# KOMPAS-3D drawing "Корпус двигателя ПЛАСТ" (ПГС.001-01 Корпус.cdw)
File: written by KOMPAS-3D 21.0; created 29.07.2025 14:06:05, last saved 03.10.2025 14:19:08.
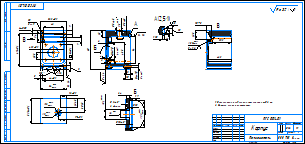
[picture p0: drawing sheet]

Sheet 1: A4x3, landscape

Document properties: Автор: rinat.gaysin.00@bk.ru; Полное имя файла: C:\Users\User\Desktop\ПЕРСПЕКТИВА кд\Чертежи\ПГС.001-01 Корпус.cdw; Знак неуказанной шероховатости: 4; Параметр неуказанной шероховатости: Ra 3.2; Масса: 0.864545; Форматы листов документа: A4@4~3

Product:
- Part/product: Корпус двигателя ПЛАСТ
    Масса: 0.864545
    Форматы листов документа: 2xA3
  - Body: Тело 1
      Масса: 0.862842

Title block, sheet 1: Наименование: Корпус; designation: ПГС.001 - 01; Материал: Полиацеталь; Масса: 0,86; Количество листов документа: 1; organisation: ООО ТПК Пегас; Форматы листов документа: A4 3; stored path: C:\Users\rinat\OneDrive\Рабочий стол\ПЕРСПЕКТИВА кд\Чертежи\Корпус двигателя ПЛАСТ.cdw

Views: Вид 1, Местный разрез 1, Спереди, Проекционный вид 2, Местный разрез 2, Местный разрез 3, Местный разрез 5, Местный разрез 6, Выносной элемент 3, Проекционный вид 4, Выносной элемент 5, Выносной элемент А, Выносной элемент, Выносной элемент Б, Вид по стрелке В
Referenced files in C:\Users\User\Desktop\ПЕРСПЕКТИВА кд\Модель\: ПГС.001 Корпус.m3d
Referenced files in C:\Users\rinat\OneDrive\Рабочий стол\П7\: Корпус двигателя ПЛАСТ.m3d
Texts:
  Ra 1.6
  Корпус двигателя ПЛАСТ
  Ra 3.2
  Ra 3.2 ( )
Dimensions and other numbers on the sheet: 54; 8; 9; 69±0,1; 6±0,05; 44±0,1; 5; 5 рад; 31±0,1; 15,5; 24; 52,3±0,1; 12; 135; 43,3±0,1; 7; 42; 80; 43,5; 15; 10; 8 отв; 0,5; 2,3; 0,3; 4; 2; 4 отв; 3,5; 1,85; 1; 18,65; 17±0,1; 30,15; 22; 8,1; 2 фаски; 0,35; 1,9; 2,4; 0,15; 1:1; 0,86

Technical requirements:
  Неуказанные предельные отклонения   0,2 мм
  Острые кромки притупить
